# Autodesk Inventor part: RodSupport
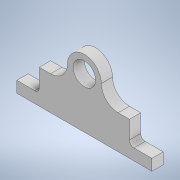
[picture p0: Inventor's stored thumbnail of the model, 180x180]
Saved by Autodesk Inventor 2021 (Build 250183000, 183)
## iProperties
Created: 2026-10
Part Number: RodSupport
Material: Generic
Document SubType Name: Modeling
Designer: hp
Density: 1 g/cm^3
Appearance: Default
Author: hp
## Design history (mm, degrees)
sketch "Sketch2"
  geometry: L1 (-20, 15)-(20, 15); L2 (20, 15)-(20, 0); L3 (20, 0)-(-20, 0); L4 (-20, 7)-(-20, 15); L5 (-20, 0)-(-30, 0); L6 (-30, 0)-(-30, 5); L7 (-30, 5)-(-22, 5); L8 (-20, 5)-(-20, 0); L9 (0, 0)-(0, 22.5); L10 (20, 5)-(20, 0); L11 (30, 5)-(22, 5); L12 (20, 0)-(30, 0); L13 (30, 0)-(30, 5); C1 r 5 at (0, 22.5); A1 r 7.5 centre (-15, 22.5) between (-15, 15) and (-7.5, 22.5); A2 r 7.5 centre (0, 22.5) between (7.5, 22.5) and (-7.5, 22.5); A3 r 7.5 centre (15, 22.5) between (7.5, 22.5) and (15, 15); A4 r 2 centre (-22, 7) between (-22, 5) and (-20, 7); A5 r 2 centre (22, 7) between (20, 7) and (22, 5); 2 further points
  constraints: 26 end point, 10 point on circle, 7 tangent, 6 centre point, 6 symmetric about line, 5 point on line, 4 parallel, 2 horizontal, 2 midpoint, 2 perpendicular, 1 coincident, 1 concentric, 1 vertical, 1 vertical alignment, 1 other
  dimensions: "d1" = 40 distance of L2.end L3.end; "d2" = 15 distance of L1.end L2.end; "d5" = 15 diameter of A1; "d6" = 15 diameter of A2; "d7" = 15 diameter of A3; "d8" = 10 diameter of C1; "d11" = 10 distance of L6.end L8.start; "d12" = 5 distance of L5.end L6.end; "d13" = 2 radius of A4 (derived)
extrude "Extrusion1" new body sketch "Sketch2" distance "d9" = 5; taper "d10" = 0 deg
body "Solid1"
